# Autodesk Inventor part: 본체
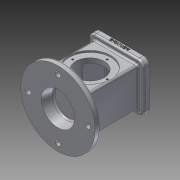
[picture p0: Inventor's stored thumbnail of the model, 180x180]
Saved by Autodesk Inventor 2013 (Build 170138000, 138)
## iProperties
Created: 2018-10
Part Number: 본체
Material: 알루미늄 6061
Document SubType Name: Modeling
Designer: Administrator
Density: 2.71 g/cm^3
Mass: 989.33 g
Surface Area: 739.56 cm^2
Volume: 365.066 cm^3
Author: Administrator
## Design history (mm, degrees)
sketch "스케치1"
  geometry: L1 (-37, -33)-(37, -33); L2 (37, -33)-(37, 33); L3 (37, 33)-(-37, 33); L4 (-37, 33)-(-37, -33); L5 (-37, -33)-(37, 33); L6 (37, -33)-(-37, 33); 1 further point
  constraints: 12 end point, 2 midpoint, 2 parallel, 1 horizontal, 1 perpendicular
  dimensions: "d1" = 74 distance of L3.end L2.end; "d2" = 66 distance of L2.end L1.end
extrude "돌출1" new body sketch "스케치1" distance "d3" = 108; taper "d4" = 0 deg
sketch "스케치2"
  geometry: L1 (37, -33)-(-37, -33) reference; L2 (37, 33)-(37, -33) reference; L3 (-37, 33)-(37, 33) reference; L4 (-37, -33)-(-37, 33) reference; C1 r 62.5 at (0, 0); 1 further point
  constraints: 1 centre point, 1 coincident
  dimensions: "d5" = 125 diameter of C1
extrude "돌출2" join sketch "스케치2" distance "d6" = 10; taper "d7" = 0 deg
sketch "스케치3"
  geometry: L1 (37, 33)-(-37, 33) reference; L2 (-37, 33)-(-37, -33) reference; L3 (-37, -33)-(37, -33) reference; L4 (37, -33)-(37, 33) reference; L5 (-46, -41)-(46, -41); L6 (46, -41)-(46, 41); L7 (46, 41)-(-46, 41); L8 (-46, 41)-(-46, -41); L9 (-46, -41)-(46, 41); L10 (46, -41)-(-46, 41); 1 further point
  constraints: 12 end point, 2 midpoint, 2 parallel, 1 horizontal, 1 perpendicular
  dimensions: "d8" = 92 distance of L7.end L6.end; "d9" = 82 distance of L6.end L5.end
extrude "돌출3" join sketch "스케치3" distance "d10" = 10; taper "d11" = 0 deg
fillet "모깎기1" dims "d12" = 10
sketch "스케치4"
  geometry: A1 r 10 centre (-36, 31) between (-36, 41) and (-46, 31) reference; A2 r 10 centre (-36, -31) between (-46, -31) and (-36, -41) reference; A3 r 10 centre (36, -31) between (36, -41) and (46, -31) reference; A4 r 10 centre (36, 31) between (46, 31) and (36, 41) reference; 5 further points
  constraints: 4 coincident
hole "구멍1" sketch "스케치4" at (-36, 31), (36, 31), (36, -31), (-36, -31) diameter "d13" = 3.242; stored, may be unused: countersink angle "d17" = 90 deg, drill point angle "d19" = 118 deg; dims "d14" = 4, "d15" = 4, "d16" = 2, "d18" = 6
sketch "스케치5"
  geometry: L1 (-26, -26)-(26, -26); L2 (26, -26)-(26, 26); L3 (26, 26)-(-26, 26); L4 (-26, 26)-(-26, -26); L5 (-26, -26)-(26, 26); L6 (26, -26)-(-26, 26); L7 (-22, -22)-(22, -22); L8 (22, -22)-(22, 22); L9 (22, 22)-(-22, 22); L10 (-22, 22)-(-22, -22); L11 (-22, -22)-(22, 22); L12 (22, -22)-(-22, 22); 1 further point
  constraints: 24 end point, 4 midpoint, 4 parallel, 2 horizontal, 2 perpendicular
  dimensions: "d20" = 52 distance of L3.end L2.end; "d21" = 52 distance of L2.end L1.end; "d22" = 44 distance of L9.end L8.end; "d23" = 44 distance of L8.end L7.end
extrude "돌출4" cut sketch "스케치5" distance "d24" = 8; taper "d25" = 0 deg
extrude "돌출5" cut sketch "스케치5" distance "d26" = 82; taper "d27" = 0 deg
sketch "스케치6"
  geometry: L1 (99.5, -10)-(-25.5, -10) reference; C1 r 35 at (37, 44); 1 further point
  constraints: 1 centre point, 1 vertical alignment
  dimensions: "d28" = 70 diameter of C1; "d29" = 54 distance from line of L1 C1.centre
extrude "돌출6" cut sketch "스케치6" distance "d30" = 3; taper "d31" = 0 deg
sketch "스케치7"
  geometry: C1 r 35 at (0, 0) reference; 2 further points
  constraints: 1 vertical alignment
  dimensions: "d32" = 29 distance of point (0, 29) C1.centre
hole "구멍2" sketch "스케치7" at (0, 29) diameter "d33" = 3.242; stored, may be unused: countersink angle "d37" = 90 deg, drill point angle "d39" = 118 deg; dims "d34" = 4, "d35" = 4, "d36" = 2, "d38" = 6
sketch "스케치8"
  geometry: L1 (62.5, -54)-(-62.5, -54) reference; C1 r 35 at (0, 0) reference; C2 r 24 at (0, 0); 1 further point
  constraints: 1 centre point, 1 coincident
  dimensions: "d44" = 48 diameter of C2 (derived); "d45" = 54 distance from line of L1 C1.centre (derived)
extrude "돌출7" cut sketch "스케치8" stored distance "d46" = 3; taper "d47" = 0 deg
sketch "스케치11"
  geometry: C1 r 62.5 at (0, 0) reference; C2 r 28 at (0, 0)
  constraints: 1 centre point, 1 coincident
  dimensions: "d49" = 56 diameter of C2 (derived)
extrude "돌출8" cut sketch "스케치11" distance "d50" = 18; taper "d51" = -10 deg
sketch "스케치12"
  geometry: L1 (37, 33)-(-37, 33) reference; L2 (0, 0)-(50, 0); C1 r 62.5 at (0, 0) reference; C2 r 4.5 at (50, 0)
  constraints: 2 end point, 1 centre point, 1 coincident, 1 parallel
  dimensions: "d54" = 50 distance of L2.start L2.end (derived); "d55" = 9 diameter of C2 (derived)
extrude "돌출9" cut sketch "스케치12" distance "d56" = 18; taper "d57" = 0 deg
chamfer "모따기1" distance "d61" = 1; stored, may be unused: second distance "d62" = 2, angle "d63" = 45 deg
fillet "모깎기2" dims "d64" = 3
fillet "모깎기4" dims "d66" = 3
fillet "모깎기5" dims "d67" = 3
fillet "모깎기6" dims "d68" = 3
fillet "모깎기7" dims "d69" = 3
sketch "스케치13"
  geometry: L1 (0, 0)-(72, 0) reference; L2 (-10, 0)-(-10, -7) reference; 2 further points
  constraints: 1 other
  dimensions: "d72" = 4 distance from line of L1 point (36, -4); "d73" = 46 distance from line of L2 point (36, -4)
feature "엠보싱1" sketch "스케치13" dims "d1" = 74, "d2" = 66, "d74" = 0.5, "d75" = 0
fillet "모깎기10" dims "d85" = 3
fillet "모깎기11" dims "d86" = 3
fillet "모깎기12" dims "d87" = 3
node "솔리드1"
pattern_circular "원형 패턴1" dims angle "d41" = 360 deg
mirror "대칭1"
pattern_circular "원형 패턴2" dims angle "d59" = 360 deg
